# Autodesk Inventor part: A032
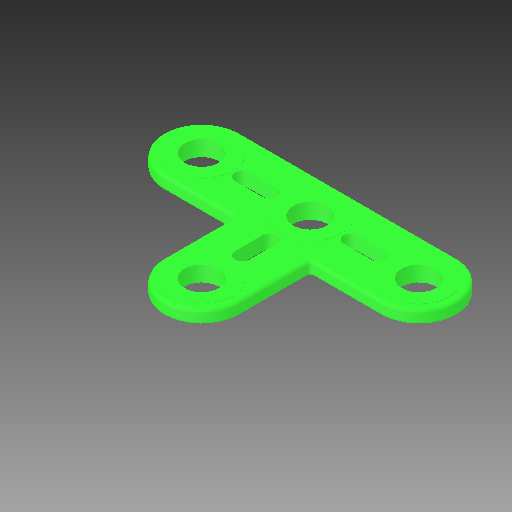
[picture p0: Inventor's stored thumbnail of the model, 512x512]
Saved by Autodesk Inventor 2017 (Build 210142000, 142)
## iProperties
Part Number: A032
Material: Générique
Document SubType Name: Modeling
Designer: ficho
Density: 1 g/cm^3
Appearance: Par défaut
Author: ficho
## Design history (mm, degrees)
feature "Solid1"
node "Solide1"
